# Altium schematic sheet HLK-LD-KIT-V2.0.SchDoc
size A3
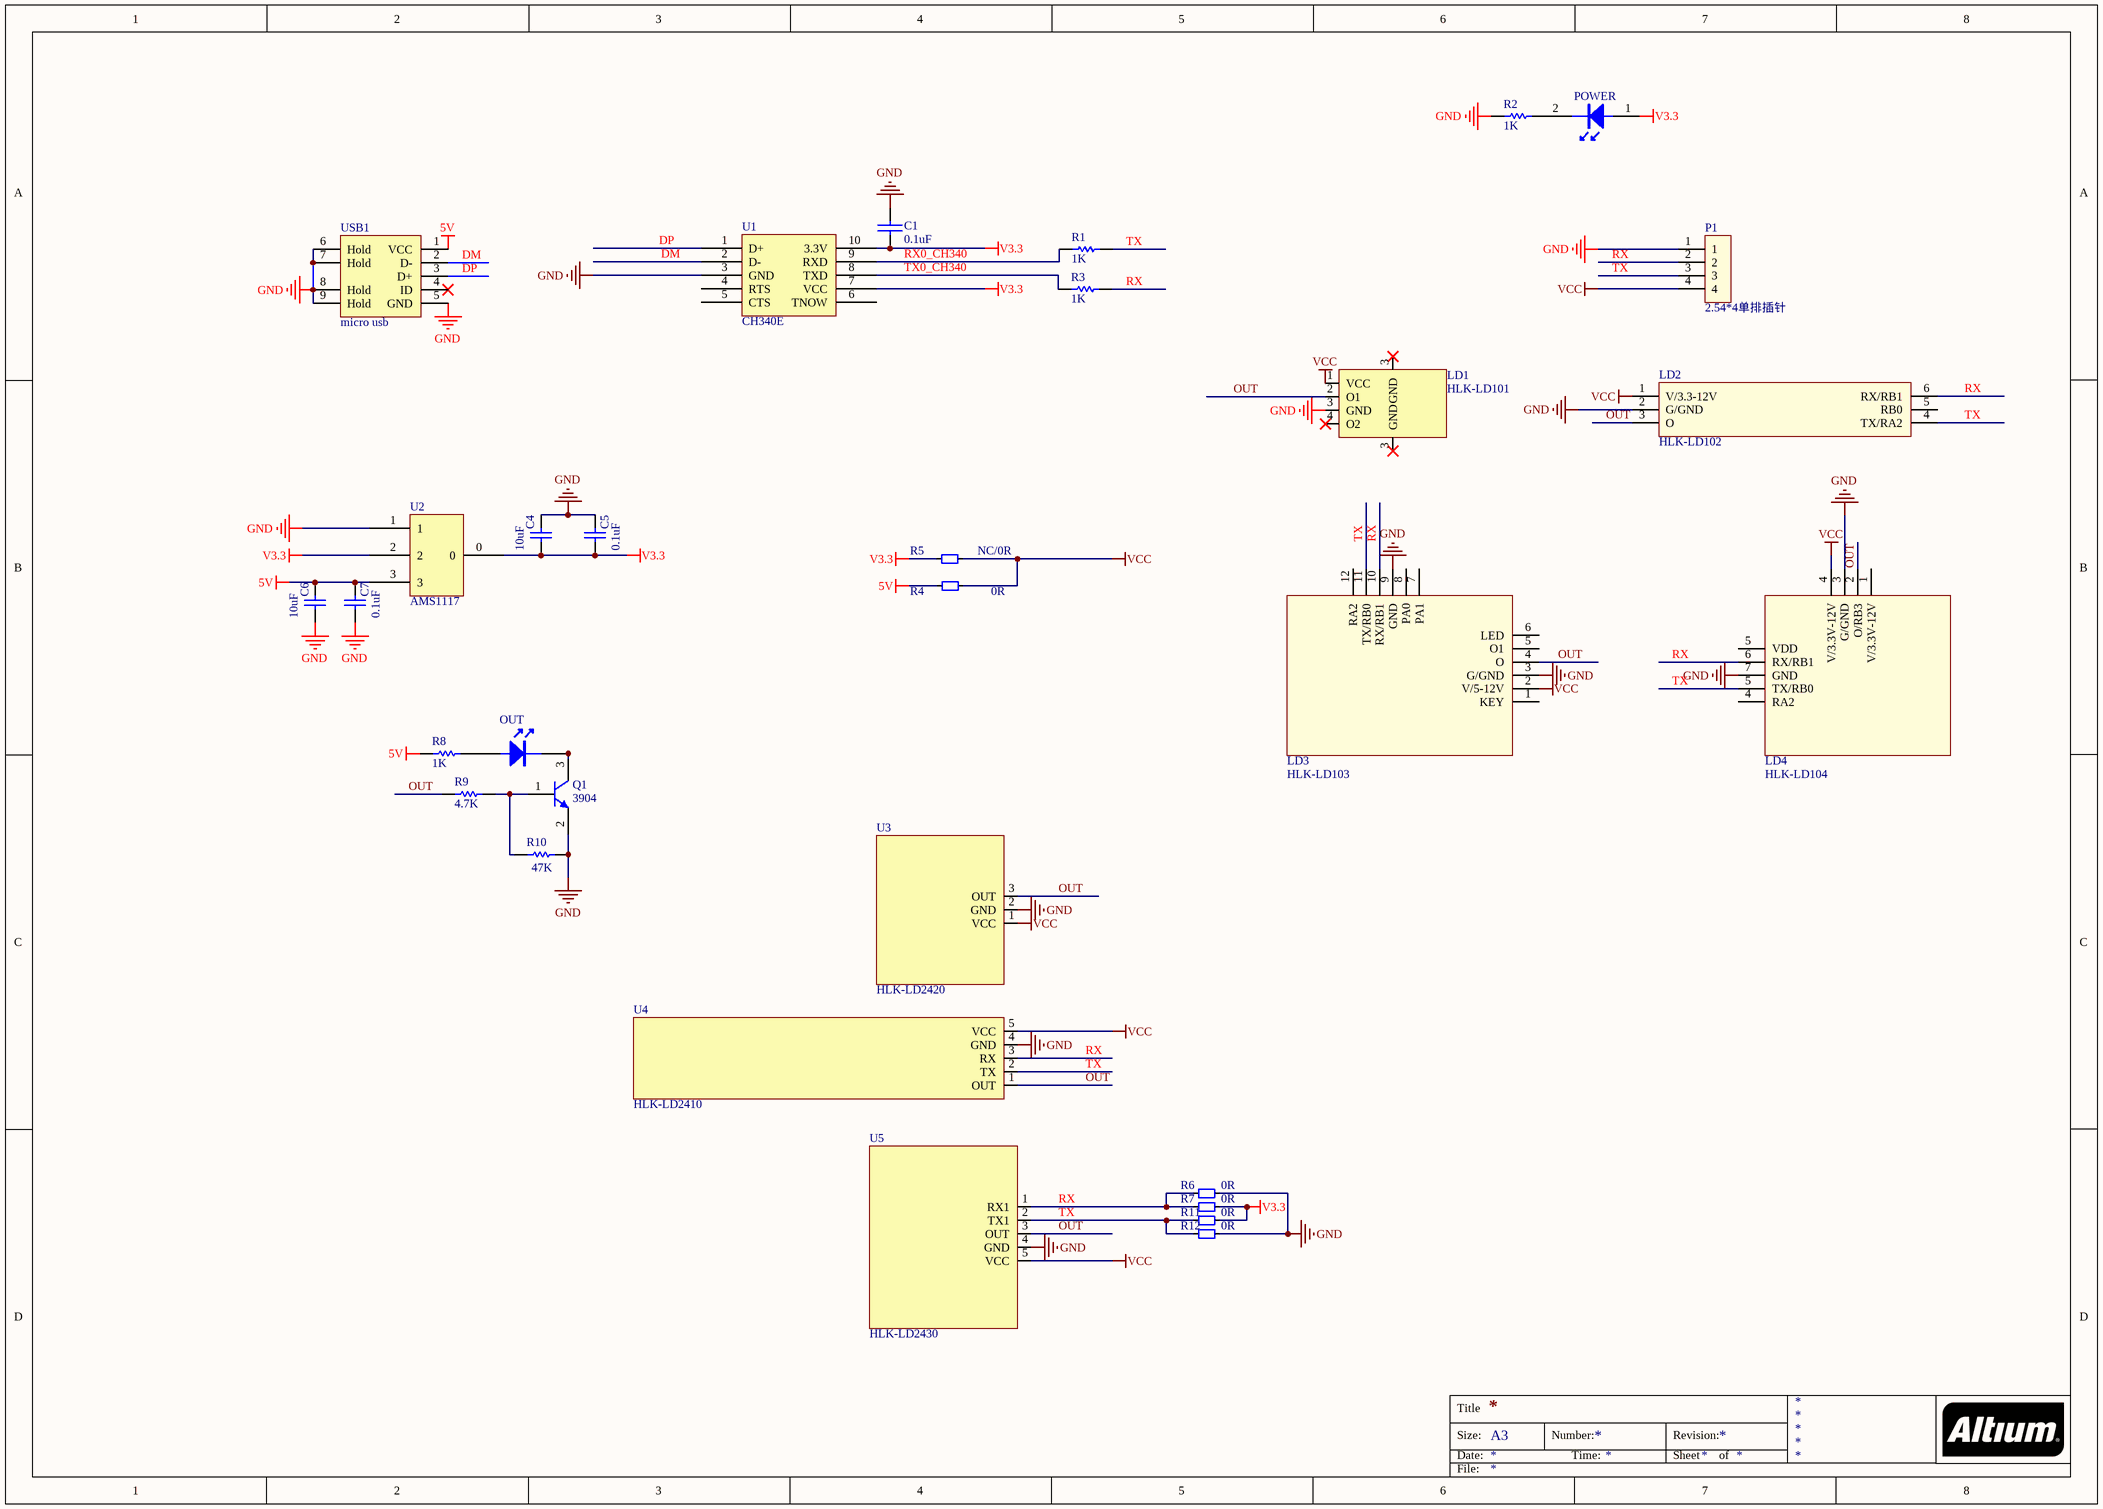
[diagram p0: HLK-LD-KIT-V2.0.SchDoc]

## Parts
C1  0.1uF  [0603]
C4  10uF  [0603]
C5  0.1uF  [0603]
C6  10uF  [0603]
C7  0.1uF  [0603]
LD1  HLK-LD101  [LD101]
LD2  HLK-LD102  [LD102]
LD3  HLK-LD103  [LD103]
LD4  HLK-LD104  [LD104]
OUT  (no value)  [0603LED]
P1  2.54*4单排插针  [SIP_4P_2.54]
POWER  LED  [0603LED]  (value not drawn)
Q1  3904  [SOT-23]
R1  1K  [0603]
R2  1K  [0603]
R3  1K  [0603]
R4  0R  [R0603]
R5  NC/0R  [R0603]
R6  0R  [R0603]
R7  0R  [R0603]
R8  1K  [0603]
R9  4.7K  [0603]
R10  47K  [0603]
R11  0R  [R0603]
R12  0R  [R0603]
U1  CH340E  [MSOP-10]
U2  AMS1117  [1117]
U3  HLK-LD2420  [HLK-LD2420]
U4  HLK-LD2410  [HLK-LD2410]
U5  HLK-LD2430  [HLK-LD2430]
USB1  micro usb  [USB-MICRO_D]

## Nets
5V: C6.1 C7.1 R4.2 R8.1 U2.3 USB1.1(VCC)
GND: C1.1 C4.1 C5.1 C6.2 C7.2 LD1.3(GND) LD2.2(G/GND) LD3.3(G/GND) LD3.9(GND) LD4.3(G/GND) LD4.7(GND) P1.1 Q1.2(E) R2.2 R6.1 R10.1 R12.1 U1.3(GND) U2.1 U3.2(GND) U4.4(GND) U5.4(GND) USB1.5(GND) USB1.6(Hold) USB1.7(Hold) USB1.8(Hold) USB1.9(Hold)
V3.3: C1.2 C4.2 C5.2 POWER.1 R5.2 R7.1 R11.1 U1.7(VCC) U1.10(3.3V) U2.0 U2.2
VCC: LD1.1(VCC) LD2.1(V/3.3-12V) LD3.2(V/5-12V) LD4.4(RA2) P1.4 R4.1 R5.1 U3.1(VCC) U4.5(VCC) U5.5(VCC)
DM: U1.2(D-) USB1.2(D-)
DP: U1.1(D+) USB1.3(D+)
OUT: LD1.2(O1) LD2.3(O) LD3.4(O) LD4.2(O/RB3) R9.2 U3.3(OUT) U4.1(OUT) U5.3(OUT)
RX: LD2.6(RX/RB1) LD3.10(RX/RB1) LD4.6(RX/RB1) P1.2 R3.1 R6.2 R7.2 U4.3(RX) U5.1(RX1)
RX0_CH340: R1.2 U1.9(RXD)
TX: LD2.4(TX/RA2) LD3.11(TX/RB0) LD4.5(TX/RB0) P1.3 R1.1 R11.2 R12.2 U4.2(TX) U5.2(TX1)
TX0_CH340: R3.2 U1.8(TXD)
NetOUT_1: OUT.1 R8.2
NetOUT_2: OUT.2 Q1.3(C)
NetPOWER_2: POWER.2 R2.1
NetQ1_1: Q1.1(B) R9.1 R10.2

Not connected (* = marked no-connect by the designer): LD1 4(O2)*; LD2 5(RB0); LD3 1(KEY) 5(O1) 6(LED) 7(PA1) 8(PA0) 12(RA2); LD4 1(V/3.3V-12V); U1 4(RTS) 5(CTS) 6(TNOW); USB1 4(ID)*

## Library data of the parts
C1 = CAP: Capacitor
C4-C7 = Cap: Capacitor; Value: 100pF
LD1 = LD101
LD2-LD4 = HLK-LD015-5G
OUT = LED
P1 = 2.54*2插针
Q1 = A09T: NPN General Purpose Amplifier
R1-R3 R8-R10 = Res1: Resistor
R4-R7 R11 R12 = R
U2 = Component_1
U3 = HLK-LD2420: 生命存在24G雷达
U4 = HLK-LD2410: 生命存在24G雷达
U5 = HLK-LD2430: 生命存在24G雷达
USB1 = USB-D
